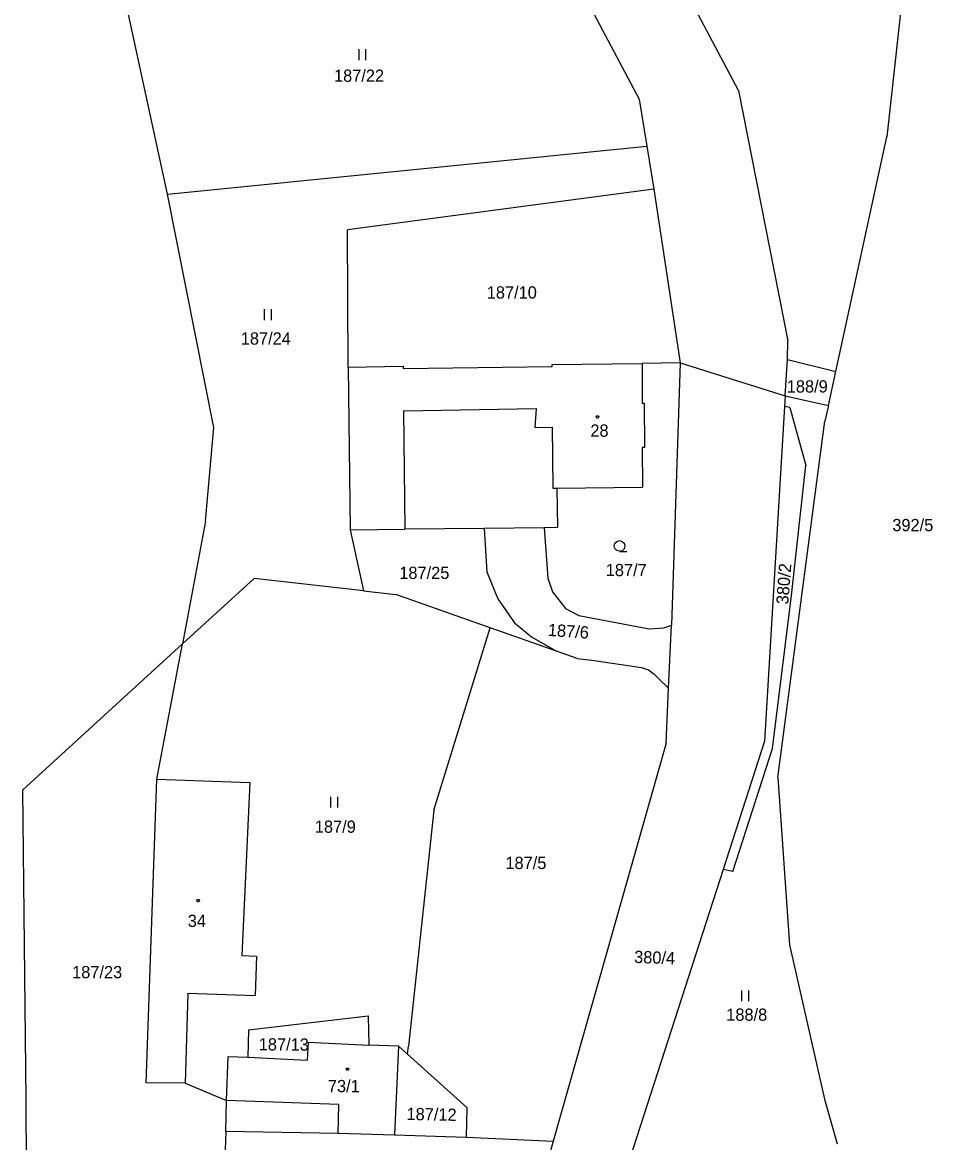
# Model space of a CAD drawing. Extents: x -811039 to -805820, y -1161436 to -1155864.
# Drawn here: x -806673 to -806546.7, y -1157883.1 to -1157727.6 of the extents above; entities that cross this region are included whole.
import ezdxf

# ---------------------------------------------------------------- set-up
doc = ezdxf.new("R2010")
doc.units = 0
for name, color, linetype in [('Default', 7, 'Continuous'), ('Hranice parcel', 7, 'Continuous'), ('Parcelní čísla', 7, 'Continuous'), ('Vnitřní kresba', 7, 'Continuous'), ('Značky budov', 7, 'Continuous'), ('Značky kultur', 7, 'Continuous')]:
    doc.layers.add(name, color=color, linetype=linetype)

# ---------------------------------------------------------------- blocks, each defined once
blk = doc.blocks.new('304')
at = {"layer": 'Default'}
blk.add_lwpolyline([(0, 0), (-0.38, 0.1), (-0.65, 0.37), (-0.75, 0.74), (-0.65, 1.11), (-0.38, 1.38), (-0.01, 1.48), (0.36, 1.38), (0.63, 1.11), (0.73, 0.73), (0.63, 0.35), (0.36, 0.08), (-0.02, -0.02), (0.98, -0.02)], dxfattribs=at)
blk = doc.blocks.new('306')
at = {"layer": 'Default'}
for p, q in [((-0.5, 1.5), (-0.5, 0)), ((0.5, 0), (0.5, 1.5))]:
    blk.add_line(p, q, dxfattribs=at)
blk = doc.blocks.new('402')
at = {"layer": 'Default'}
blk.add_lwpolyline([(0.09, 0.15), (0.18, 0), (0.09, -0.15), (-0.09, -0.15), (-0.18, 0), (-0.09, 0.15), (0.09, 0.15)], dxfattribs=at)

msp = doc.modelspace()

# ---------------------------------------------------------------- linework, layer by layer
at = {"layer": 'Hranice parcel'}
for p, q in [((-806573.63, -1157737.11), (-806605.65, -1157676.97)), ((-806549.38, -1157710.12), (-806553.08, -1157743.51)), ((-806598.27, -1157717.88), (-806587.43, -1157738.28)), ((-806652.88, -1157751.49), (-806658.86, -1157723.93)), ((-806573.63, -1157737.11), (-806566.78, -1157771.82)), ((-806587.43, -1157738.28), (-806586.37, -1157744.82)), ((-806560.15, -1157776.09), (-806553.08, -1157743.51)), ((-806652.88, -1157751.49), (-806586.37, -1157744.82)), ((-806586.37, -1157744.82), (-806585.4, -1157750.78)), ((-806646.47, -1157783.84), (-806652.88, -1157751.49)), ((-806585.4, -1157750.78), (-806627.9, -1157756.44)), ((-806585.4, -1157750.78), (-806581.76, -1157774.87)), ((-806627.81, -1157775.49), (-806627.9, -1157756.44)), ((-806566.87, -1157774.43), (-806566.78, -1157771.82)), ((-806599.49, -1157775.1), (-806587.01, -1157774.97)), ((-806587.01, -1157774.97), (-806587.04, -1157780.48)), ((-806581.76, -1157774.87), (-806587.01, -1157774.97)), ((-806581.76, -1157774.87), (-806582.95, -1157811.26)), ((-806581.76, -1157774.87), (-806567.16, -1157779.47)), ((-806567.16, -1157779.47), (-806566.87, -1157774.43)), ((-806566.87, -1157774.43), (-806560.15, -1157776.09)), ((-806627.81, -1157775.49), (-806620.17, -1157775.36)), ((-806627.81, -1157775.49), (-806627.56, -1157798.04)), ((-806620.17, -1157775.36), (-806620.17, -1157775.65)), ((-806620.17, -1157775.65), (-806599.49, -1157775.4)), ((-806599.49, -1157775.4), (-806599.49, -1157775.1)), ((-806561.17, -1157780.8), (-806560.15, -1157776.09)), ((-806567.16, -1157779.47), (-806567.25, -1157780.95)), ((-806567.16, -1157779.47), (-806561.17, -1157780.8)), ((-806587.04, -1157780.48), (-806586.72, -1157780.47)), ((-806586.72, -1157780.47), (-806586.69, -1157786.6)), ((-806567.25, -1157780.95), (-806570.03, -1157827.34)), ((-806566.51, -1157781.05), (-806567.25, -1157780.95)), ((-806566.51, -1157781.05), (-806564.32, -1157789.13)), ((-806561.17, -1157780.8), (-806561.66, -1157782.99)), ((-806647.62, -1157796.82), (-806646.47, -1157783.84)), ((-806568.2, -1157832.4), (-806561.66, -1157782.99)), ((-806586.69, -1157786.6), (-806587.01, -1157786.62)), ((-806587.01, -1157786.62), (-806586.98, -1157792.11)), ((-806566.3, -1157807.17), (-806564.32, -1157789.13)), ((-806598.84, -1157792.26), (-806586.98, -1157792.11)), ((-806598.84, -1157792.26), (-806598.77, -1157797.7)), ((-806647.62, -1157796.82), (-806650.83, -1157813.86)), ((-806627.56, -1157798.04), (-806619.95, -1157797.95)), ((-806627.56, -1157798.04), (-806625.69, -1157806.51)), ((-806608.95, -1157797.84), (-806619.95, -1157797.95)), ((-806600.61, -1157797.78), (-806608.95, -1157797.84)), ((-806608.95, -1157797.84), (-806608.59, -1157803.89)), ((-806598.77, -1157797.7), (-806600.61, -1157797.78)), ((-806600.61, -1157797.78), (-806600.12, -1157804.74)), ((-806608.59, -1157803.89), (-806607.06, -1157807.61)), ((-806640.85, -1157804.79), (-806650.83, -1157813.86)), ((-806625.69, -1157806.51), (-806640.85, -1157804.79)), ((-806600.12, -1157804.74), (-806599.47, -1157806.63)), ((-806625.69, -1157806.51), (-806621.19, -1157807.02)), ((-806608.1, -1157811.62), (-806621.19, -1157807.02)), ((-806607.06, -1157807.61), (-806604.74, -1157810.94)), ((-806599.47, -1157806.63), (-806597.66, -1157808.95)), ((-806568.91, -1157828.39), (-806566.3, -1157807.17)), ((-806597.66, -1157808.95), (-806595.83, -1157809.92)), ((-806595.83, -1157809.92), (-806586.05, -1157811.78)), ((-806615.94, -1157836.95), (-806608.1, -1157811.62)), ((-806598.89, -1157814.86), (-806608.1, -1157811.62)), ((-806604.74, -1157810.94), (-806602.37, -1157812.91)), ((-806586.05, -1157811.78), (-806584.01, -1157811.65)), ((-806584.01, -1157811.65), (-806582.95, -1157811.26)), ((-806583.38, -1157820), (-806582.95, -1157811.26)), ((-806650.83, -1157813.86), (-806673.04, -1157834.14)), ((-806654.38, -1157832.63), (-806650.83, -1157813.86)), ((-806602.37, -1157812.91), (-806598.89, -1157814.86)), ((-806596.03, -1157815.9), (-806598.89, -1157814.86)), ((-806596.03, -1157815.9), (-806593.99, -1157816.14)), ((-806593.99, -1157816.14), (-806587.09, -1157817.14)), ((-806587.09, -1157817.14), (-806586.15, -1157817.46)), ((-806586.15, -1157817.46), (-806585.36, -1157818.07)), ((-806585.36, -1157818.07), (-806584.65, -1157818.76)), ((-806584.65, -1157818.76), (-806583.38, -1157820)), ((-806583.67, -1157827.65), (-806583.38, -1157820)), ((-806583.67, -1157827.65), (-806599.35, -1157882.87)), ((-806570.03, -1157827.34), (-806575.79, -1157845.15)), ((-806574.44, -1157845.44), (-806568.91, -1157828.39)), ((-806568.2, -1157832.4), (-806566.58, -1157855.63)), ((-806655.88, -1157874.75), (-806654.38, -1157832.63)), ((-806654.38, -1157832.63), (-806641.47, -1157833.11)), ((-806641.47, -1157833.11), (-806642.59, -1157857.11)), ((-806673.04, -1157834.14), (-806672.55, -1157877.06)), ((-806615.94, -1157836.95), (-806619.47, -1157869.66)), ((-806575.79, -1157845.15), (-806588.75, -1157885.25)), ((-806574.44, -1157845.44), (-806575.79, -1157845.15)), ((-806566.58, -1157855.63), (-806561.71, -1157877.02)), ((-806642.59, -1157857.11), (-806640.53, -1157857.18)), ((-806640.53, -1157857.18), (-806640.73, -1157862.64)), ((-806650.07, -1157862.3), (-806650.43, -1157874.79)), ((-806650.07, -1157862.3), (-806640.73, -1157862.64)), ((-806641.64, -1157867.42), (-806625.04, -1157865.47)), ((-806625.04, -1157865.47), (-806624.95, -1157869.54)), ((-806641.64, -1157867.42), (-806641.77, -1157871.21)), ((-806633.39, -1157869.12), (-806633.51, -1157871.6)), ((-806633.39, -1157869.12), (-806624.95, -1157869.54)), ((-806620.84, -1157869.67), (-806624.95, -1157869.54)), ((-806620.84, -1157869.67), (-806621.39, -1157881.98)), ((-806620.84, -1157869.67), (-806619.59, -1157870.79)), ((-806619.59, -1157870.79), (-806619.47, -1157869.66)), ((-806644.69, -1157877.22), (-806644.5, -1157871.11)), ((-806644.5, -1157871.11), (-806641.77, -1157871.21)), ((-806641.77, -1157871.21), (-806633.51, -1157871.6)), ((-806619.59, -1157870.79), (-806611.32, -1157878.24)), ((-806650.43, -1157874.79), (-806655.88, -1157874.75)), ((-806650.43, -1157874.79), (-806644.69, -1157877.22)), ((-806672.55, -1157877.06), (-806672.48, -1157889.17)), ((-806644.79, -1157881.45), (-806644.69, -1157877.22)), ((-806561.71, -1157877.02), (-806559.95, -1157883.23)), ((-806611.42, -1157882.28), (-806611.32, -1157878.24)), ((-806644.79, -1157881.45), (-806644.96, -1157885.34)), ((-806644.79, -1157881.45), (-806629.22, -1157881.72)), ((-806629.22, -1157881.72), (-806621.39, -1157881.98)), ((-806621.39, -1157881.98), (-806611.42, -1157882.28)), ((-806611.42, -1157882.28), (-806599.35, -1157882.87)), ((-806599.35, -1157882.87), (-806603.42, -1157897.19))]:
    msp.add_line(p, q, dxfattribs=at)
at = {"layer": 'Vnitřní kresba'}
for p, q in [((-806620.14, -1157781.52), (-806601.73, -1157781.21)), ((-806601.73, -1157781.21), (-806601.91, -1157783.85)), ((-806620.14, -1157781.52), (-806619.95, -1157797.95)), ((-806601.91, -1157783.85), (-806599.51, -1157783.79)), ((-806599.51, -1157783.79), (-806599.41, -1157792.27)), ((-806599.41, -1157792.27), (-806598.84, -1157792.26)), ((-806629.11, -1157877.75), (-806644.69, -1157877.22)), ((-806629.22, -1157881.72), (-806629.11, -1157877.75))]:
    msp.add_line(p, q, dxfattribs=at)

# ---------------------------------------------------------------- block references
at = {"layer": 'Značky budov'}
for p in [(-806593.21, -1157782.38), (-806648.63, -1157849.48), (-806627.9, -1157872.87)]:
    msp.add_blockref('402', p, dxfattribs=at)
at = {"layer": 'Značky kultur'}
for name, p in [('306', (-806625.85, -1157732.87)), ('306', (-806638.98, -1157768.94)), ('304', (-806590.14, -1157801.02)), ('306', (-806629.76, -1157836.57)), ('306', (-806572.71, -1157863.44))]:
    msp.add_blockref(name, p, dxfattribs=at)

# ---------------------------------------------------------------- texts
at = {"layer": 'Parcelní čísla'}
for s, p in [('187/22', (-806629.79, -1157735.89)), ('187/10', (-806608.59, -1157765.96)), ('187/24', (-806642.73, -1157772.35)), ('188/9', (-806566.95, -1157779)), ('28', (-806594.21, -1157785.13)), ('392/5', (-806552.3, -1157798.23)), ('187/7', (-806592.07, -1157804.47)), ('187/25', (-806620.73, -1157804.86)), ('187/9', (-806632.45, -1157840.07)), ('187/5', (-806606, -1157845.1)), ('34', (-806650.09, -1157853.14)), ('187/23', (-806666.14, -1157860.25)), ('188/8', (-806575.35, -1157866.15)), ('73/1', (-806630.64, -1157876.06))]:
    msp.add_text(s, height=1.7, dxfattribs=at).set_placement(p)
for s, rotation, p in [('380/2', 85.6, (-806566.74, -1157808.43)), ('187/6', 355.979, (-806600.15, -1157812.75)), ('380/4', 357.984, (-806588.16, -1157858.12)), ('187/13', 359.646, (-806640.24, -1157870.26)), ('187/12', 358.901, (-806619.74, -1157879.91))]:
    msp.add_text(s, height=1.7, rotation=rotation, dxfattribs=at).set_placement(p)

doc.saveas('drawing.dxf')
